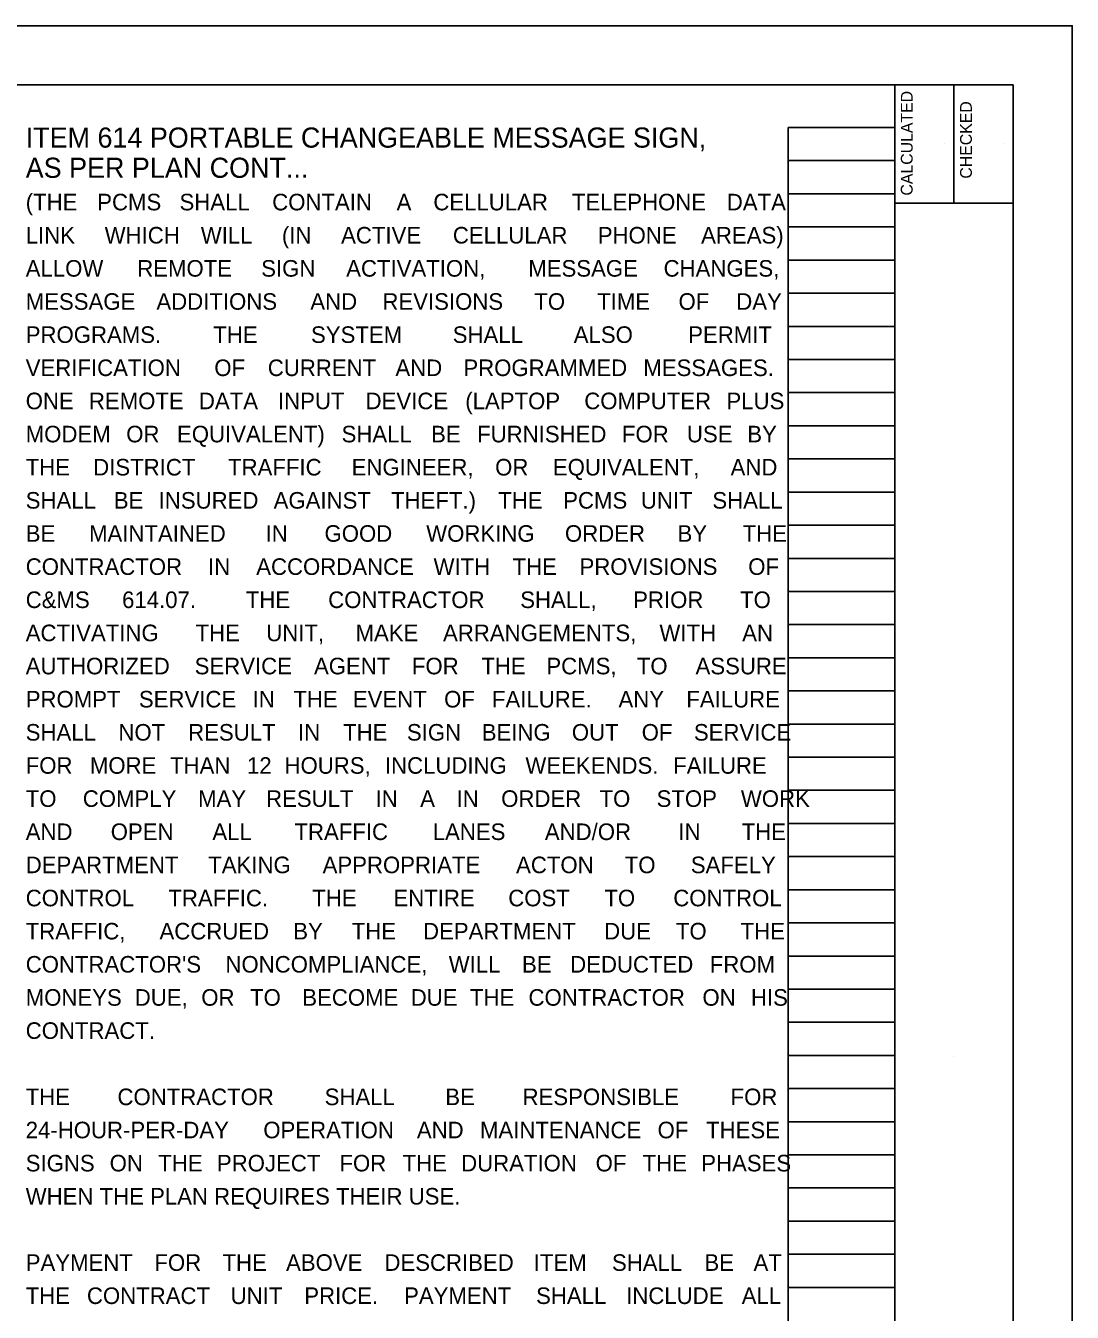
# Model space of a CAD drawing. Extents: x 0 to 34, y 0 to 22.
# Drawn here: x 25.16 to 34, y 11.13 to 22 of the extents above; entities that cross this region are included whole.
import ezdxf

# ---------------------------------------------------------------- set-up
doc = ezdxf.new("R2010")
doc.units = 0
for name, color, linetype in [('BD_P_Text', 7, 'Continuous'), ('SH_Border', 7, 'Continuous'), ('SH_Cut_Line', 7, 'Continuous'), ('SH_Data', 7, 'Continuous')]:
    doc.layers.add(name, color=color, linetype=linetype)

msp = doc.modelspace()

# ---------------------------------------------------------------- linework, layer by layer
at = {"layer": 'SH_Border'}
for p, q in [((32.5, 0.5), (32.5, 21.5)), ((33, 21.5), (33, 20.5)), ((32.5, 20.5), (33.5, 20.5))]:
    msp.add_line(p, q, dxfattribs=at)
msp.add_lwpolyline([(2, 21.5), (33.5, 21.5), (33.5, 0.5), (2, 0.5)], close=True, dxfattribs=at)
at = {"layer": 'SH_Cut_Line'}
msp.add_lwpolyline([(0, 0), (34, 0), (34, 22), (0, 22)], close=True, dxfattribs=at)
at = {"layer": 'SH_Data'}
for p, q in [((31.6, 0.98), (31.6, 21.14)), ((31.6, 21.14), (32.5, 21.14)), ((32.5, 0.98), (32.5, 21.14)), ((32.92, 21.004), (32.92, 21.004)), ((33.42, 21.004), (33.42, 21.004)), ((31.6, 20.86), (32.5, 20.86)), ((31.6, 20.58), (32.5, 20.58)), ((31.6, 20.3), (32.5, 20.3)), ((31.6, 20.02), (32.5, 20.02)), ((31.6, 19.74), (32.5, 19.74)), ((31.6, 19.46), (32.5, 19.46)), ((31.6, 19.18), (32.5, 19.18)), ((31.6, 18.9), (32.5, 18.9)), ((31.6, 18.62), (32.5, 18.62)), ((31.6, 18.34), (32.5, 18.34)), ((31.6, 18.06), (32.5, 18.06)), ((31.6, 17.78), (32.5, 17.78)), ((31.6, 17.5), (32.5, 17.5)), ((31.6, 17.22), (32.5, 17.22)), ((31.6, 16.94), (32.5, 16.94)), ((31.6, 16.66), (32.5, 16.66)), ((31.6, 16.38), (32.5, 16.38)), ((31.6, 16.1), (32.5, 16.1)), ((31.6, 15.82), (32.5, 15.82)), ((31.6, 15.54), (32.5, 15.54)), ((31.6, 15.26), (32.5, 15.26)), ((31.6, 14.98), (32.5, 14.98)), ((31.6, 14.7), (32.5, 14.7)), ((31.6, 14.42), (32.5, 14.42)), ((31.6, 14.14), (32.5, 14.14)), ((31.6, 13.86), (32.5, 13.86)), ((31.6, 13.58), (32.5, 13.58)), ((31.6, 13.3), (32.5, 13.3)), ((33, 13.292), (33, 13.292)), ((31.6, 13.02), (32.5, 13.02)), ((31.6, 12.74), (32.5, 12.74)), ((31.6, 12.46), (32.5, 12.46)), ((31.6, 12.18), (32.5, 12.18)), ((31.6, 11.9), (32.5, 11.9)), ((31.6, 11.62), (32.5, 11.62)), ((31.6, 11.34), (32.5, 11.34))]:
    msp.add_line(p, q, dxfattribs=at)

# ---------------------------------------------------------------- texts
at = {"layer": 'BD_P_Text'}
for s, height, p in [('ITEM 614 PORTABLE CHANGEABLE MESSAGE SIGN,', 0.17, (25.16, 20.97)), ('AS PER PLAN CONT...', 0.17, (25.16, 20.715)), ('(THE ', 0.14, (25.16, 20.44)), ('PCMS ', 0.14, (25.764, 20.44)), ('SHALL ', 0.14, (26.459, 20.44)), ('CONTAIN ', 0.14, (27.242, 20.44)), ('A ', 0.14, (28.293, 20.44)), ('CELLULAR ', 0.14, (28.603, 20.44)), ('TELEPHONE ', 0.14, (29.773, 20.44)), ('DATA ', 0.14, (31.082, 20.44)), ('LINK ', 0.14, (25.16, 20.16)), ('WHICH ', 0.14, (25.827, 20.16)), ('WILL ', 0.14, (26.639, 20.16)), ('(IN ', 0.14, (27.324, 20.16)), ('ACTIVE ', 0.14, (27.824, 20.16)), ('CELLULAR ', 0.14, (28.768, 20.16)), ('PHONE ', 0.14, (29.992, 20.16)), ('AREAS) ', 0.14, (30.865, 20.16)), ('ALLOW ', 0.14, (25.16, 19.88)), ('REMOTE ', 0.14, (26.102, 19.88)), ('SIGN ', 0.14, (27.149, 19.88)), ('ACTIVATION, ', 0.14, (27.867, 19.88)), ('MESSAGE ', 0.14, (29.405, 19.88)), ('CHANGES, ', 0.14, (30.548, 19.88)), ('MESSAGE ', 0.14, (25.16, 19.6)), ('ADDITIONS ', 0.14, (26.264, 19.6)), ('AND ', 0.14, (27.564, 19.6)), ('REVISIONS ', 0.14, (28.173, 19.6)), ('TO ', 0.14, (29.456, 19.6)), ('TIME ', 0.14, (29.987, 19.6)), ('OF ', 0.14, (30.674, 19.6)), ('DAY ', 0.14, (31.162, 19.6)), ('PROGRAMS. ', 0.14, (25.16, 19.32)), (' THE ', 0.14, (26.692, 19.32)), ('SYSTEM ', 0.14, (27.57, 19.32)), ('SHALL ', 0.14, (28.767, 19.32)), ('ALSO ', 0.14, (29.789, 19.32)), ('PERMIT ', 0.14, (30.756, 19.32)), ('VERIFICATION ', 0.14, (25.16, 19.04)), ('OF ', 0.14, (26.753, 19.04)), ('CURRENT ', 0.14, (27.205, 19.04)), ('AND ', 0.14, (28.283, 19.04)), ('PROGRAMMED ', 0.14, (28.857, 19.04)), ('MESSAGES. ', 0.14, (30.377, 19.04)), ('ONE ', 0.14, (25.16, 18.76)), ('REMOTE ', 0.14, (25.694, 18.76)), ('DATA ', 0.14, (26.623, 18.76)), ('INPUT ', 0.14, (27.291, 18.76)), ('DEVICE ', 0.14, (28.031, 18.76)), ('(LAPTOP ', 0.14, (28.873, 18.76)), ('COMPUTER ', 0.14, (29.878, 18.76)), ('PLUS ', 0.14, (31.079, 18.76)), ('MODEM ', 0.14, (25.16, 18.48)), ('OR ', 0.14, (26.009, 18.48)), ('EQUIVALENT) ', 0.14, (26.438, 18.48)), ('SHALL ', 0.14, (27.828, 18.48)), ('BE ', 0.14, (28.584, 18.48)), ('FURNISHED ', 0.14, (28.973, 18.48)), ('FOR ', 0.14, (30.196, 18.48)), ('USE ', 0.14, (30.745, 18.48)), ('BY ', 0.14, (31.255, 18.48)), ('THE ', 0.14, (25.16, 18.2)), ('DISTRICT ', 0.14, (25.73, 18.2)), ('TRAFFIC ', 0.14, (26.869, 18.2)), ('ENGINEER, ', 0.14, (27.913, 18.2)), ('OR ', 0.14, (29.125, 18.2)), ('EQUIVALENT, ', 0.14, (29.613, 18.2)), ('AND ', 0.14, (31.114, 18.2)), ('SHALL ', 0.14, (25.16, 17.92)), ('BE ', 0.14, (25.904, 17.92)), ('INSURED ', 0.14, (26.283, 17.92)), ('AGAINST ', 0.14, (27.254, 17.92)), ('THEFT.) ', 0.14, (28.246, 17.92)), (' THE ', 0.14, (29.099, 17.92)), ('PCMS ', 0.14, (29.7, 17.92)), ('UNIT ', 0.14, (30.356, 17.92)), ('SHALL ', 0.14, (30.96, 17.92)), ('BE ', 0.14, (25.16, 17.64)), ('MAINTAINED ', 0.14, (25.695, 17.64)), ('IN ', 0.14, (27.186, 17.64)), ('GOOD ', 0.14, (27.684, 17.64)), ('WORKING ', 0.14, (28.543, 17.64)), ('ORDER ', 0.14, (29.715, 17.64)), ('BY ', 0.14, (30.666, 17.64)), ('THE ', 0.14, (31.216, 17.64)), ('CONTRACTOR ', 0.14, (25.16, 17.36)), ('ACCORDANCE ', 0.14, (27.107, 17.36)), ('PROVISIONS ', 0.14, (29.838, 17.36)), ('OF ', 0.14, (31.263, 17.36)), ('IN ', 0.14, (26.7, 17.36)), ('WITH ', 0.14, (28.605, 17.36)), ('THE ', 0.14, (29.272, 17.36)), ('C&MS ', 0.14, (25.16, 17.08)), ('614.07. ', 0.14, (25.974, 17.08)), (' THE ', 0.14, (26.967, 17.08)), ('CONTRACTOR ', 0.14, (27.715, 17.08)), ('SHALL, ', 0.14, (29.337, 17.08)), ('PRIOR ', 0.14, (30.291, 17.08)), ('TO ', 0.14, (31.194, 17.08)), ('ACTIVATING ', 0.14, (25.16, 16.8)), ('THE ', 0.14, (26.594, 16.8)), ('UNIT, ', 0.14, (27.192, 16.8)), ('MAKE ', 0.14, (27.946, 16.8)), ('ARRANGEMENTS, ', 0.14, (28.685, 16.8)), ('WITH ', 0.14, (30.513, 16.8)), ('AN ', 0.14, (31.212, 16.8)), ('AUTHORIZED ', 0.14, (25.16, 16.52)), ('SERVICE ', 0.14, (26.587, 16.52)), ('AGENT ', 0.14, (27.595, 16.52)), ('FOR ', 0.14, (28.422, 16.52)), ('THE ', 0.14, (29.009, 16.52)), ('PCMS, ', 0.14, (29.558, 16.52)), ('TO ', 0.14, (30.322, 16.52)), ('ASSURE ', 0.14, (30.818, 16.52)), ('PROMPT ', 0.14, (25.16, 16.24)), ('SERVICE ', 0.14, (26.116, 16.24)), ('IN ', 0.14, (27.077, 16.24)), ('THE ', 0.14, (27.421, 16.24)), ('EVENT ', 0.14, (27.923, 16.24)), ('OF ', 0.14, (28.694, 16.24)), ('FAILURE. ', 0.14, (29.098, 16.24)), (' ANY ', 0.14, (30.115, 16.24)), ('FAILURE ', 0.14, (30.74, 16.24)), ('SHALL ', 0.14, (25.16, 15.96)), ('NOT ', 0.14, (25.943, 15.96)), ('RESULT ', 0.14, (26.532, 15.96)), ('IN ', 0.14, (27.46, 15.96)), ('THE ', 0.14, (27.841, 15.96)), ('SIGN ', 0.14, (28.38, 15.96)), ('BEING ', 0.14, (29.012, 15.96)), ('OUT ', 0.14, (29.773, 15.96)), ('OF ', 0.14, (30.363, 15.96)), ('SERVICE ', 0.14, (30.804, 15.96)), ('FOR ', 0.14, (25.16, 15.68)), ('MORE ', 0.14, (25.702, 15.68)), ('THAN ', 0.14, (26.379, 15.68)), ('12 ', 0.14, (27.029, 15.68)), ('HOURS, ', 0.14, (27.346, 15.68)), ('INCLUDING ', 0.14, (28.194, 15.68)), ('WEEKENDS. ', 0.14, (29.381, 15.68)), (' FAILURE ', 0.14, (30.577, 15.68)), ('TO ', 0.14, (25.16, 15.4)), ('COMPLY ', 0.14, (25.642, 15.4)), ('MAY ', 0.14, (26.616, 15.4)), ('RESULT ', 0.14, (27.19, 15.4)), ('IN ', 0.14, (28.115, 15.4)), ('A ', 0.14, (28.492, 15.4)), ('IN ', 0.14, (28.799, 15.4)), ('ORDER ', 0.14, (29.176, 15.4)), ('TO ', 0.14, (30.007, 15.4)), ('STOP ', 0.14, (30.489, 15.4)), ('WORK ', 0.14, (31.201, 15.4)), ('AND ', 0.14, (25.16, 15.12)), ('OPEN ', 0.14, (25.878, 15.12)), ('ALL ', 0.14, (26.737, 15.12)), ('TRAFFIC ', 0.14, (27.43, 15.12)), ('LANES ', 0.14, (28.598, 15.12)), ('AND/OR ', 0.14, (29.545, 15.12)), ('IN ', 0.14, (30.673, 15.12)), ('THE ', 0.14, (31.208, 15.12)), ('DEPARTMENT ', 0.14, (25.16, 14.84)), ('TAKING ', 0.14, (26.702, 14.84)), ('APPROPRIATE ', 0.14, (27.668, 14.84)), ('ACTON ', 0.14, (29.302, 14.84)), ('TO ', 0.14, (30.22, 14.84)), ('SAFELY ', 0.14, (30.778, 14.84)), ('CONTROL ', 0.14, (25.16, 14.56)), ('TRAFFIC. ', 0.14, (26.365, 14.56)), (' THE ', 0.14, (27.529, 14.56)), ('ENTIRE ', 0.14, (28.266, 14.56)), ('COST ', 0.14, (29.236, 14.56)), ('TO ', 0.14, (30.048, 14.56)), ('CONTROL ', 0.14, (30.63, 14.56)), ('TRAFFIC, ', 0.14, (25.16, 14.28)), ('ACCRUED ', 0.14, (26.29, 14.28)), ('BY ', 0.14, (27.42, 14.28)), ('THE ', 0.14, (27.914, 14.28)), ('DEPARTMENT ', 0.14, (28.516, 14.28)), ('DUE ', 0.14, (30.046, 14.28)), ('TO ', 0.14, (30.652, 14.28)), ('THE ', 0.14, (31.199, 14.28)), ("CONTRACTOR'S ", 0.14, (25.16, 14)), ('NONCOMPLIANCE, ', 0.14, (26.847, 14)), ('WILL ', 0.14, (28.733, 14)), ('BE ', 0.14, (29.352, 14)), ('DEDUCTED ', 0.14, (29.759, 14)), ('FROM ', 0.14, (30.938, 14)), ('MONEYS ', 0.14, (25.16, 13.72)), ('DUE, ', 0.14, (26.081, 13.72)), ('OR ', 0.14, (26.643, 13.72)), ('TO ', 0.14, (27.055, 13.72)), ('BECOME ', 0.14, (27.496, 13.72)), ('DUE ', 0.14, (28.412, 13.72)), ('THE ', 0.14, (28.912, 13.72)), ('CONTRACTOR ', 0.14, (29.407, 13.72)), ('ON ', 0.14, (30.876, 13.72)), ('HIS ', 0.14, (31.286, 13.72)), ('CONTRACT.', 0.14, (25.16, 13.44)), ('THE ', 0.14, (25.16, 12.88)), ('CONTRACTOR ', 0.14, (25.935, 12.88)), ('SHALL ', 0.14, (27.685, 12.88)), ('BE ', 0.14, (28.704, 12.88)), ('RESPONSIBLE ', 0.14, (29.357, 12.88)), ('FOR ', 0.14, (31.114, 12.88)), ('24-HOUR-PER-DAY ', 0.14, (25.16, 12.6)), ('OPERATION ', 0.14, (27.167, 12.6)), ('AND ', 0.14, (28.464, 12.6)), ('MAINTENANCE ', 0.14, (28.997, 12.6)), ('OF ', 0.14, (30.497, 12.6)), ('THESE ', 0.14, (30.907, 12.6)), ('SIGNS ', 0.14, (25.16, 12.32)), ('ON ', 0.14, (25.869, 12.32)), ('THE ', 0.14, (26.28, 12.32)), ('PROJECT ', 0.14, (26.775, 12.32)), ('FOR ', 0.14, (27.81, 12.32)), ('THE ', 0.14, (28.343, 12.32)), ('DURATION ', 0.14, (28.838, 12.32)), ('OF ', 0.14, (29.974, 12.32)), ('THE ', 0.14, (30.371, 12.32)), ('PHASES ', 0.14, (30.866, 12.32)), ('WHEN THE PLAN REQUIRES THEIR USE.', 0.14, (25.16, 12.04)), ('PAYMENT ', 0.14, (25.16, 11.48)), ('FOR ', 0.14, (26.247, 11.48)), ('THE ', 0.14, (26.822, 11.48)), ('ABOVE ', 0.14, (27.359, 11.48)), ('DESCRIBED ', 0.14, (28.19, 11.48)), ('ITEM ', 0.14, (29.451, 11.48)), ('SHALL ', 0.14, (30.112, 11.48)), ('BE ', 0.14, (30.893, 11.48)), ('AT ', 0.14, (31.308, 11.48)), ('THE ', 0.14, (25.16, 11.2)), ('CONTRACT ', 0.14, (25.677, 11.2)), ('UNIT ', 0.14, (26.891, 11.2)), ('PRICE. ', 0.14, (27.513, 11.2)), (' PAYMENT ', 0.14, (28.304, 11.2)), ('SHALL ', 0.14, (29.471, 11.2)), ('INCLUDE ', 0.14, (30.232, 11.2)), ('ALL ', 0.14, (31.208, 11.2))]:
    msp.add_text(s, height=height, dxfattribs=at).set_placement(p)
at = {"layer": 'SH_Data'}
for s, p in [('CALCULATED', (32.652, 20.565)), ('CHECKED', (33.152, 20.708))]:
    msp.add_text(s, height=0.1, rotation=90, dxfattribs=at).set_placement(p)

doc.saveas('drawing.dxf')
